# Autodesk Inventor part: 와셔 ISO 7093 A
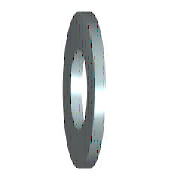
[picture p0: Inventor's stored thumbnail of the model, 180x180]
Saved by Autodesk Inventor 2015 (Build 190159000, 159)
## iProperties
Created: 2012-02
Part Number: 와셔 ISO 7093 A
Material: 스테인리스강
Description: 평면 와셔 - 대형 시리즈 - 제품 등급 A
Document SubType Name: Modeling
Standard: ISO 7093 A
Designer: mduedu
Standard Revision: First Edition 2000-06-01
Standards Organization: ISO
Language: ko-KR
Size Designation: ST 4 - 140 HV - A
Categories: <MemberInstance><Categories><Category DisplayName="조임쇠" InternalName="e4da775c-781d-43d5-af7c-5136215cf5a6" Mnemonic="FSTN"><Category DisplayName="와셔" InternalN
Density: 8.08 g/cm^3
Appearance: 파란색 - 벽 페인트 - 광택
Mass: 0.796489 g
Surface Area: 2.48359 cm^2
Volume: 0.0985753 cm^3
IsCustomPart: 1
Author: mduedu
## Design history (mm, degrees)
sketch "스케치"
  geometry: C1 r 6 at (0, 0); C2 r 2.15 at (0, 0); 1 further point
  constraints: 2 centre point, 2 coincident
  dimensions: "d0" = 4.3 diameter of C2 (= SD1); "d1" = 12 diameter of C1 (= SD2)
extrude "본체" new body sketch "스케치" distance "d2" = 1 (= SD); taper "d3" = 0 deg
workaxis "Work Axis1"
workplane "Work Plane1"
body "Solid1"
other parameters: "SD1" = 4.3 [user parameter; used in 1 equation term], "SD2" = 12 [user parameter; used in 1 equation term], "SD" = 1 [user parameter; used in 1 equation term], "d4" = 0, "d5" = 0, "d6" = 0, "d7" = 0, "NND" = 4 [user parameter]
